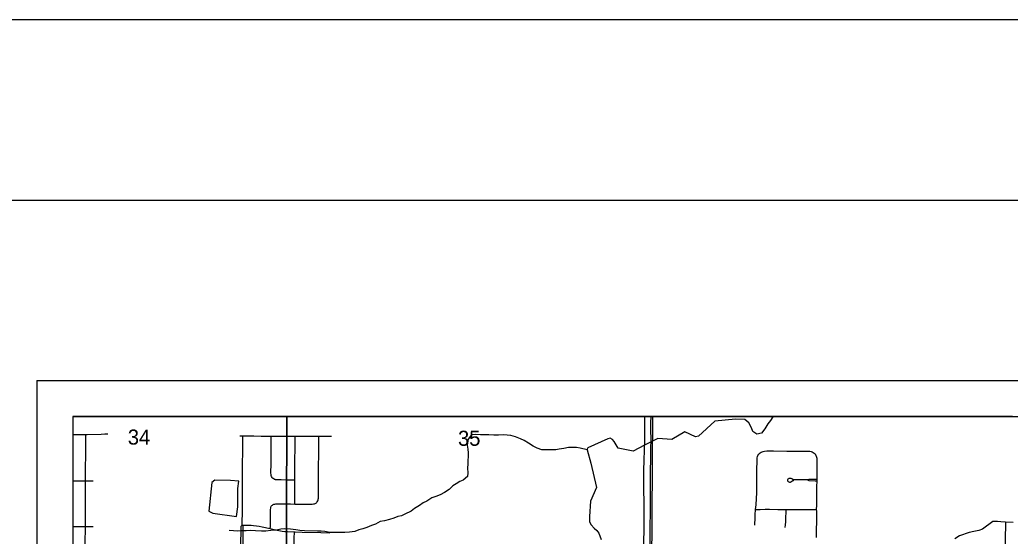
# Model space of a CAD drawing. Extents: x 0 to 34, y 0 to 22.
# Drawn here: x 1.953 to 4.702, y 20.568 to 22 of the extents above; entities that cross this region are included whole.
import ezdxf

# ---------------------------------------------------------------- set-up
doc = ezdxf.new("R2010")
doc.units = 0
for name, color, linetype in [('Default', 7, 'Continuous'), ('GM_X_City_Street', 7, 'Continuous'), ('GM_X_Interstate_Route', 7, 'Continuous'), ('GM_X_Minor_Lake', 7, 'Continuous'), ('GM_X_Minor_River', 7, 'Continuous'), ('GM_X_Section_Text', 7, 'Continuous'), ('SH_Border', 7, 'Continuous'), ('SH_Cut_Line', 7, 'Continuous'), ('SH_Data', 7, 'Continuous')]:
    doc.layers.add(name, color=color, linetype=linetype)

msp = doc.modelspace()

# ---------------------------------------------------------------- linework, layer by layer
at = {"layer": 'Default'}
for points in [[(2.6946, 20.9), (2.1, 20.9), (2.1, 20.3537), (2.6925, 20.3513)], [(3.7106, 20.9), (2.6946, 20.9), (2.6925, 20.3513), (3.7003, 20.3485), (3.7064, 20.3481)]]:
    msp.add_lwpolyline(points, close=True, dxfattribs=at)
msp.add_lwpolyline([(4.7088, 20.9), (2.1, 20.9), (2.1, 19.9153)], dxfattribs=at)
at = {"layer": 'GM_X_City_Street'}
for points in [[(3.7005, 20.3468), (3.7011, 20.3515), (3.7014, 20.354), (3.7015, 20.3564), (3.702, 20.3885), (3.7022, 20.432), (3.7024, 20.4553), (3.7024, 20.4616), (3.7026, 20.4867), (3.7029, 20.5345), (3.7032, 20.5718), (3.7036, 20.657), (3.7042, 20.7415), (3.7045, 20.7888), (3.705, 20.8155), (3.7053, 20.8304), (3.7052, 20.8683), (3.7052, 20.8826), (3.7054, 20.9)], [(2.1, 20.8498), (2.1149, 20.8497), (2.1321, 20.8497), (2.1366, 20.8497), (2.14, 20.8497), (2.1791, 20.8512), (2.1892, 20.8516), (2.1978, 20.8519)], [(2.1337, 20.4983), (2.135, 20.5946), (2.135, 20.5975), (2.1351, 20.6197), (2.1354, 20.6681), (2.1354, 20.7156), (2.1354, 20.721), (2.1354, 20.7306), (2.1355, 20.7425), (2.1357, 20.7646), (2.1359, 20.7849), (2.1359, 20.7886), (2.136, 20.7992), (2.1362, 20.8055), (2.1365, 20.8224), (2.1366, 20.8454), (2.1366, 20.8497)], [(2.5634, 20.8462), (2.5722, 20.8461), (2.5814, 20.8461), (2.6025, 20.8458), (2.623, 20.8457), (2.6509, 20.8456), (2.659, 20.8456), (2.6801, 20.8457), (2.7043, 20.8454), (2.7173, 20.8454), (2.7333, 20.8453), (2.7639, 20.8454), (2.7796, 20.8454), (2.7835, 20.8453), (2.7993, 20.8452), (2.8182, 20.8451)], [(2.5703, 20.5988), (2.5705, 20.6081), (2.5709, 20.6324), (2.571, 20.6778), (2.5712, 20.7064), (2.5716, 20.7574), (2.5719, 20.8133), (2.5722, 20.8355), (2.5722, 20.8438), (2.5722, 20.8461)], [(2.6479, 20.5887), (2.6483, 20.5914), (2.6488, 20.5942), (2.6491, 20.5974), (2.6492, 20.6002), (2.6493, 20.6116), (2.6494, 20.622), (2.6494, 20.6262), (2.6494, 20.6351), (2.6494, 20.6421), (2.6495, 20.6453), (2.6497, 20.6474), (2.6502, 20.6491), (2.6511, 20.6507), (2.6528, 20.6526), (2.6546, 20.6542), (2.6568, 20.6555), (2.6585, 20.6562), (2.6609, 20.6568), (2.6639, 20.6572), (2.6665, 20.6574), (2.6911, 20.6572), (2.7048, 20.6572), (2.7162, 20.6571), (2.7246, 20.657), (2.7301, 20.657), (2.7345, 20.657), (2.7382, 20.6569), (2.7419, 20.6569), (2.7487, 20.6569), (2.7555, 20.6568), (2.7593, 20.6568), (2.7648, 20.6569), (2.7685, 20.6573), (2.7709, 20.6579), (2.7732, 20.6588), (2.7749, 20.6597), (2.7766, 20.6608), (2.778, 20.662), (2.7789, 20.6633), (2.7802, 20.6655), (2.781, 20.6678), (2.7816, 20.6704), (2.782, 20.6737), (2.7822, 20.6765), (2.7823, 20.6796), (2.7824, 20.7019), (2.7825, 20.7173), (2.7826, 20.7491), (2.7826, 20.7614), (2.7826, 20.7745), (2.7827, 20.7813), (2.7834, 20.8214), (2.7834, 20.8343), (2.7835, 20.8432), (2.7835, 20.8453)], [(2.7162, 20.7236), (2.7143, 20.7236), (2.7052, 20.7236), (2.6917, 20.7236), (2.6788, 20.7238), (2.6708, 20.7238), (2.6672, 20.7238), (2.6655, 20.7239), (2.664, 20.7241), (2.6627, 20.7244), (2.6615, 20.7248), (2.6602, 20.7254), (2.6588, 20.7261), (2.6567, 20.7274), (2.6548, 20.729), (2.6533, 20.731), (2.6521, 20.7332), (2.651, 20.7361), (2.6506, 20.7385), (2.6503, 20.7422), (2.6502, 20.7491), (2.6504, 20.7633), (2.6507, 20.7863), (2.6507, 20.7919), (2.6507, 20.8018), (2.6508, 20.8205), (2.6508, 20.8336), (2.6509, 20.8391), (2.6509, 20.8456)], [(2.7162, 20.6571), (2.7162, 20.6591), (2.7162, 20.6773), (2.7162, 20.6904), (2.7161, 20.7084), (2.7162, 20.7236), (2.7164, 20.7469), (2.7169, 20.7885), (2.717, 20.8021), (2.7171, 20.8238), (2.7173, 20.8406), (2.7173, 20.8454)], [(3.994, 20.5983), (3.9945, 20.6192), (3.9949, 20.6286), (3.9957, 20.6402), (3.9958, 20.6423), (3.9968, 20.655), (3.9989, 20.689), (3.9992, 20.7063), (3.9994, 20.7168), (3.9995, 20.7375), (3.9995, 20.7571), (3.9996, 20.7716), (3.9997, 20.7812), (4.0002, 20.7855), (4.001, 20.7885), (4.0022, 20.7914), (4.0047, 20.7953)], [(4.0047, 20.7953), (4.0059, 20.7967), (4.0082, 20.7988), (4.0107, 20.8006), (4.0135, 20.802), (4.0165, 20.8029), (4.0201, 20.8036), (4.0269, 20.8042), (4.0347, 20.8042), (4.0456, 20.8043), (4.0823, 20.804), (4.1072, 20.804), (4.134, 20.8039), (4.1427, 20.8038), (4.1464, 20.8034), (4.1495, 20.8028), (4.1524, 20.8018), (4.1552, 20.8004), (4.1583, 20.7983), (4.1612, 20.7958), (4.1633, 20.7927)], [(4.1651, 20.5641), (4.1652, 20.5815), (4.1653, 20.6119), (4.1653, 20.6337), (4.1653, 20.6374), (4.1652, 20.6417), (4.1654, 20.6541), (4.1656, 20.6603), (4.1658, 20.6752), (4.1658, 20.6858), (4.166, 20.6982), (4.166, 20.7044), (4.1662, 20.7215), (4.1663, 20.7262), (4.1665, 20.7399), (4.1669, 20.7666), (4.1667, 20.7777), (4.1663, 20.7832), (4.1659, 20.7862), (4.1652, 20.7884), (4.1633, 20.7927)], [(2.1, 20.7213), (2.1001, 20.7213), (2.133, 20.721), (2.1354, 20.721), (2.146, 20.721), (2.1568, 20.7209)], [(4.1008, 20.7238), (4.0992, 20.7215), (4.0964, 20.7192), (4.0935, 20.7176), (4.092, 20.7171), (4.0904, 20.717), (4.0888, 20.7174), (4.0874, 20.7182), (4.0862, 20.7193), (4.0854, 20.7206), (4.085, 20.7222), (4.085, 20.7238), (4.0855, 20.7254), (4.0863, 20.7267), (4.0875, 20.7278), (4.0889, 20.7286), (4.0905, 20.729), (4.0921, 20.729), (4.0937, 20.7286), (4.0963, 20.7275), (4.0989, 20.726), (4.1013, 20.7246), (4.1064, 20.7248), (4.1195, 20.7247), (4.1344, 20.7247), (4.1377, 20.7246)], [(4.1377, 20.7246), (4.1435, 20.7262), (4.16, 20.7262), (4.1663, 20.7262)], [(4.1377, 20.7246), (4.1431, 20.7219), (4.1608, 20.7216), (4.1662, 20.7215)], [(3.9958, 20.6423), (4.0009, 20.6423), (4.008, 20.6422), (4.0226, 20.6425), (4.0345, 20.6425), (4.0574, 20.6422), (4.0805, 20.6421), (4.0984, 20.6421), (4.117, 20.6418), (4.1406, 20.642), (4.1518, 20.6418), (4.1537, 20.6418), (4.1652, 20.6417)], [(4.0781, 20.5918), (4.0786, 20.5997), (4.0792, 20.6072), (4.08, 20.6226), (4.0802, 20.6313), (4.0805, 20.6421)], [(2.1, 20.5946), (2.1098, 20.5946), (2.1305, 20.5946), (2.135, 20.5946), (2.1514, 20.5947), (2.1563, 20.5948)], [(2.5651, 20.3475), (2.5651, 20.354), (2.5651, 20.366), (2.5652, 20.3857), (2.5652, 20.4056), (2.5659, 20.4696), (2.5662, 20.4864), (2.5666, 20.5473), (2.5671, 20.5833), (2.5673, 20.5917), (2.5673, 20.5929), (2.5675, 20.5947), (2.5678, 20.5959), (2.5684, 20.597), (2.5691, 20.5979), (2.5703, 20.5988)], [(2.5703, 20.5988), (2.5764, 20.5987), (2.5844, 20.5986), (2.5895, 20.5984), (2.5955, 20.5981), (2.6016, 20.5975), (2.6097, 20.5967), (2.6178, 20.5955), (2.6257, 20.594), (2.6479, 20.5887), (2.659, 20.5861), (2.6718, 20.5835), (2.681, 20.5819), (2.6884, 20.5811), (2.6964, 20.5806), (2.7157, 20.5801), (2.7175, 20.5801), (2.7368, 20.5793), (2.789, 20.5776), (2.8138, 20.5768)], [(2.5715, 20.3475), (2.5715, 20.364), (2.5718, 20.4053), (2.5719, 20.4345), (2.572, 20.4532), (2.5723, 20.4831), (2.5726, 20.5023), (2.5726, 20.5316), (2.5729, 20.5553), (2.5731, 20.5832), (2.5732, 20.5922), (2.5732, 20.5942), (2.5728, 20.5959), (2.5723, 20.5971), (2.5716, 20.5978), (2.5703, 20.5988)], [(2.7132, 20.5008), (2.7132, 20.5031), (2.7135, 20.5113), (2.7139, 20.5271), (2.7151, 20.5628), (2.7156, 20.5786), (2.7157, 20.5801)]]:
    msp.add_lwpolyline(points, dxfattribs=at)
at = {"layer": 'GM_X_Interstate_Route'}
msp.add_lwpolyline([(4.7088, 20.9), (2.1, 20.9), (2.1, 14.3639)], dxfattribs=at)
at = {"layer": 'GM_X_Minor_Lake'}
msp.add_line((2.5582, 20.6496), (2.558, 20.6746), dxfattribs=at)
msp.add_lwpolyline([(2.558, 20.6746), (2.5578, 20.7), (2.5606, 20.7201), (2.5379, 20.7225), (2.494, 20.7228), (2.4864, 20.7168), (2.478, 20.6368), (2.4893, 20.6314), (2.5543, 20.6227), (2.5582, 20.6496)], dxfattribs=at)
at = {"layer": 'GM_X_Minor_River'}
msp.add_line((2.3372, 20.9), (2.335, 20.8986), dxfattribs=at)
for points in [[(3.6832, 20.3723), (3.6859, 20.609), (3.6854, 20.7501), (3.6879, 20.8351), (3.6883, 20.9)], [(4.0453, 20.9), (4.0438, 20.8991), (4.0368, 20.889), (4.0299, 20.8793), (4.0217, 20.8657), (4.0117, 20.8534), (3.9988, 20.8505), (3.9879, 20.8583), (3.9839, 20.8682), (3.9766, 20.8824), (3.9654, 20.8917), (3.94, 20.8921)], [(3.94, 20.8921), (3.8824, 20.8866), (3.8368, 20.8452), (3.8284, 20.8434), (3.7988, 20.8576), (3.7632, 20.8361), (3.7247, 20.8386), (3.6873, 20.8203), (3.6557, 20.8033), (3.6142, 20.8123), (3.6027, 20.8307), (3.5983, 20.8361), (3.5919, 20.8393), (3.5858, 20.8378), (3.5302, 20.8126), (3.5279, 20.8088), (3.5278, 20.8069), (3.5386, 20.7707), (3.5538, 20.7025), (3.5377, 20.6652), (3.5347, 20.6224), (3.5345, 20.608), (3.5389, 20.5992), (3.5475, 20.5903), (3.5549, 20.5838), (3.5609, 20.5761), (3.5667, 20.5589)], [(3.5278, 20.8069), (3.5086, 20.8118), (3.4981, 20.8138), (3.4879, 20.814), (3.4765, 20.8134), (3.4632, 20.8106), (3.4507, 20.8089), (3.4408, 20.8075), (3.4268, 20.807), (3.4155, 20.8076), (3.4026, 20.8078), (3.3891, 20.8122), (3.3782, 20.8173), (3.3655, 20.8255), (3.3531, 20.8329), (3.3433, 20.8376), (3.3287, 20.8431), (3.3162, 20.8467), (3.306, 20.8477), (3.2951, 20.8486), (3.2822, 20.8484), (3.2686, 20.8479), (3.255, 20.8489), (3.2433, 20.8494), (3.2315, 20.8492), (3.2176, 20.8495), (3.207, 20.8489), (3.1981, 20.8373), (3.1948, 20.8206), (3.1969, 20.8092), (3.1978, 20.7993), (3.1973, 20.7883), (3.1968, 20.7785), (3.1966, 20.7682), (3.196, 20.7569), (3.197, 20.7436), (3.1957, 20.7337), (3.1841, 20.7229), (3.1746, 20.7193), (3.1643, 20.7134), (3.1548, 20.7071), (3.1448, 20.6974), (3.1322, 20.6888), (3.1199, 20.6826), (3.1078, 20.6778), (3.0964, 20.6739), (3.0834, 20.6653), (3.0731, 20.6602), (3.0627, 20.6528), (3.049, 20.6446), (3.0394, 20.6376), (3.0223, 20.6291), (3.0127, 20.6247), (3.0021, 20.6223), (2.991, 20.6175), (2.9789, 20.6143), (2.9656, 20.6103), (2.9535, 20.6086), (2.9401, 20.6013), (2.9294, 20.5976), (2.9165, 20.5918), (2.9055, 20.5885), (2.8944, 20.5857), (2.883, 20.5809), (2.8682, 20.5789), (2.855, 20.578), (2.8391, 20.5778), (2.8247, 20.5785), (2.8141, 20.5782), (2.7994, 20.5804), (2.7896, 20.5817), (2.7794, 20.5822), (2.7435, 20.5828), (2.7306, 20.5838), (2.7197, 20.5855), (2.7042, 20.5876), (2.6872, 20.5879), (2.6773, 20.5877), (2.6659, 20.5848), (2.6496, 20.5832), (2.6356, 20.5815), (2.6239, 20.5813), (2.6073, 20.5827), (2.5929, 20.5833), (2.5815, 20.5828), (2.5668, 20.5826), (2.5562, 20.5813), (2.546, 20.5829), (2.5339, 20.5835)], [(4.7104, 20.6055), (4.6895, 20.6065), (4.6766, 20.6074), (4.6668, 20.6083), (4.6547, 20.6089), (4.6256, 20.5874), (4.6157, 20.5837), (4.602, 20.5809), (4.5888, 20.5785), (4.5621, 20.569), (4.5488, 20.5609)], [(4.6895, 20.6065), (4.6859, 20.4032), (4.6868, 20.2468), (4.6906, 20.0609), (4.6928, 19.9561)]]:
    msp.add_lwpolyline(points, dxfattribs=at)
at = {"layer": 'SH_Border'}
msp.add_lwpolyline([(1.5, 21.5), (33.5, 21.5), (33.5, 0.5), (1.5, 0.5)], close=True, dxfattribs=at)
at = {"layer": 'SH_Cut_Line'}
msp.add_lwpolyline([(0, 0), (34, 0), (34, 22), (0, 22)], close=True, dxfattribs=at)
at = {"layer": 'SH_Data'}
for p, q in [((2, 21), (9, 21)), ((2, 21), (2, 14)), ((2.1, 20.9), (2.1, 14.1)), ((2.1, 20.9), (8.9, 20.9))]:
    msp.add_line(p, q, dxfattribs=at)

# ---------------------------------------------------------------- texts
at = {"layer": 'GM_X_Section_Text'}
for s, p in [('34', (2.2528, 20.8218)), ('35', (3.1695, 20.8185))]:
    msp.add_text(s, height=0.04186, rotation=0, dxfattribs=at).set_placement(p)

doc.saveas('drawing.dxf')
